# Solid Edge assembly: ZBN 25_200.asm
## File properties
Title: Zylinder
Author: bmolnar
Template: iso metric assembly.asm
Last saved by: bmolnar
Revision: 25
Application: Solid Edge
Username: bmolnar
Dokumentum tartalom típus: 1
Document Number: ZBN 25/200
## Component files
Profilrohr.par
Kolbenstange.par
Kit_2.par
Kit_1.par
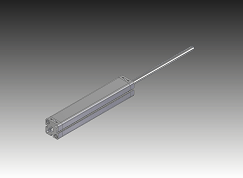
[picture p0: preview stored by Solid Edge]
